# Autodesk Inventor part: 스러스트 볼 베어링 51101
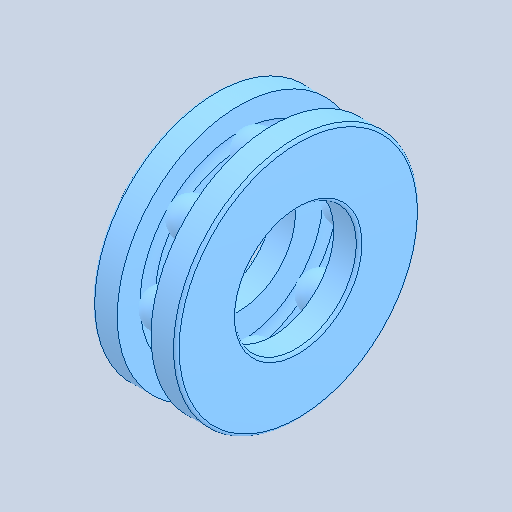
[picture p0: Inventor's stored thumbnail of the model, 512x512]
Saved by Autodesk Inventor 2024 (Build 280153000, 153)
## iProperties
Created: 2024-08
Part Number: 스러스트 볼 베어링 51101
Material: 강철, 연강
Description: 롤링 베어링 - 플랫 뒷면이 있는 스러스트 볼 베어링
Document SubType Name: Modeling
Designer: user
Density: 7.85 g/cm^3
Appearance: 기본값
Author: jhkim
Sending System: Autodesk Inventor 2025
Preprocessor: ST-DEVELOPER v20
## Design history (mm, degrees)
feature "Solid1"
feature "Solid1:1"
feature "Solid1:2"
feature "Solid1:3"
feature "Solid1:4"
feature "Solid1:5"
feature "Solid1:6"
feature "Solid1:7"
feature "Solid1:8"
feature "Solid1:9"
node "솔리드1"
node "솔리드2"
node "솔리드3"
node "솔리드4"
node "솔리드5"
node "솔리드6"
node "솔리드7"
node "솔리드8"
node "솔리드9"
node "솔리드10"
